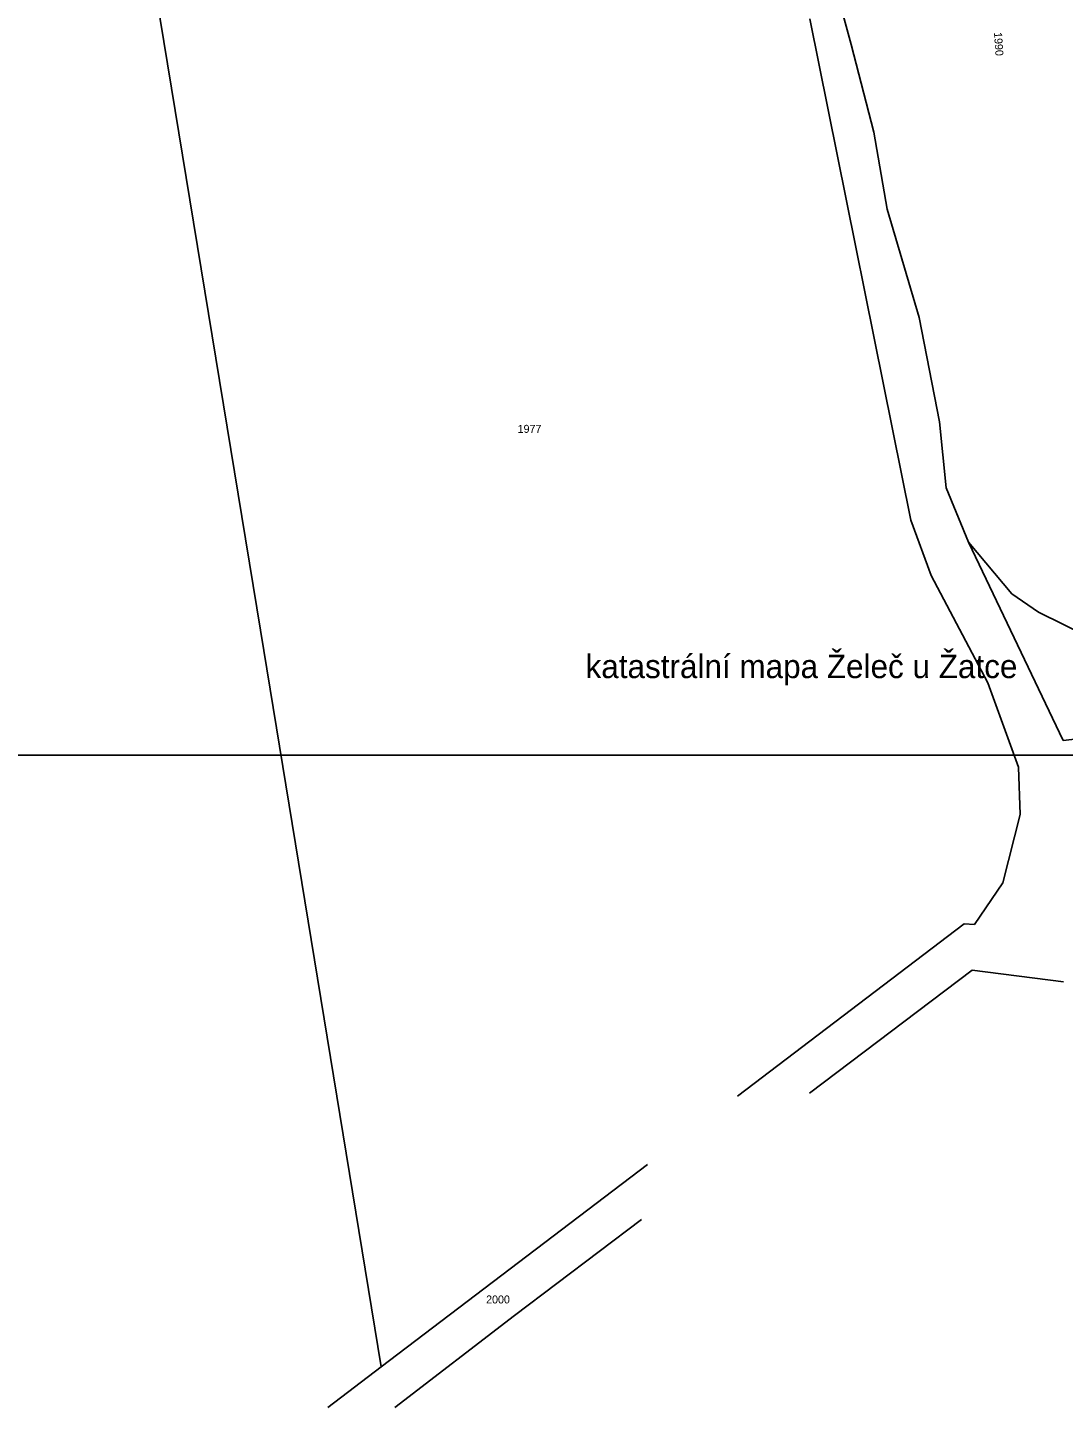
# Model space of a CAD drawing. Extents: x -801853 to -800578, y -1017479 to -1016338.
# Drawn here: x -801170.2 to -800950, y -1017477.7 to -1017184.4 of the extents above; entities that cross this region are included whole.
import ezdxf

# ---------------------------------------------------------------- set-up
doc = ezdxf.new("R2010")
doc.units = 0
for name, color, linetype in [('KLADY_ZMVM', 7, 'Continuous'), ('KN_HRANICE', 7, 'Continuous'), ('KN_PARCELY', 7, 'Continuous'), ('LEGENDA', 7, 'Continuous')]:
    doc.layers.add(name, color=color, linetype=linetype)

msp = doc.modelspace()

# ---------------------------------------------------------------- linework, layer by layer
at = {"layer": 'KN_HRANICE'}
for p, q in [((-801147.67, -1017148.04), (-801120.7, -1017312.51)), ((-801003.34, -1017158.2), (-800995.15, -1017188.06)), ((-801003.97, -1017182.58), (-800982.5, -1017289.15)), ((-800995.15, -1017188.06), (-800990.37, -1017206.68)), ((-800990.37, -1017206.68), (-800987.47, -1017223.03)), ((-800987.47, -1017223.03), (-800980.69, -1017246.06)), ((-800980.69, -1017246.06), (-800976.35, -1017268.19)), ((-800976.35, -1017268.19), (-800974.93, -1017282.28)), ((-800974.93, -1017282.28), (-800970.19, -1017293.76)), ((-800982.5, -1017289.15), (-800978.12, -1017300.9)), ((-800970.19, -1017293.76), (-800961.01, -1017304.78)), ((-800970.19, -1017293.76), (-800950.06, -1017335.93)), ((-800978.12, -1017300.9), (-800966.08, -1017323.69)), ((-800961.01, -1017304.78), (-800955.36, -1017308.64)), ((-800955.36, -1017308.64), (-800944.74, -1017313.92)), ((-801120.7, -1017312.51), (-801095.04, -1017469.02)), ((-800966.08, -1017323.69), (-800959.58, -1017341.61)), ((-800939.16, -1017334.66), (-800950.06, -1017335.93)), ((-800959.58, -1017341.61), (-800959.25, -1017351.67)), ((-800959.25, -1017351.67), (-800962.93, -1017366.17)), ((-800962.93, -1017366.17), (-800968.91, -1017375.05)), ((-801019.33, -1017411.52), (-800971.13, -1017374.91)), ((-800971.13, -1017374.91), (-800968.91, -1017375.05)), ((-801004.03, -1017410.86), (-800969.41, -1017384.77)), ((-800969.41, -1017384.77), (-800950.02, -1017387.19)), ((-801095.04, -1017469.02), (-801038.43, -1017426.03)), ((-801066.73, -1017458.1), (-801039.69, -1017437.72)), ((-801092.18, -1017477.65), (-801066.73, -1017458.1)), ((-801106.41, -1017477.65), (-801095.04, -1017469.02))]:
    msp.add_line(p, q, dxfattribs=at)
at = {"layer": 'LEGENDA'}
msp.add_lwpolyline([(-801559.16, -1017339.08), (-800718.16, -1017339.08), (-800718.16, -1016745.08), (-801559.16, -1016745.08)], close=True, dxfattribs=at)

# ---------------------------------------------------------------- texts
at = {"layer": 'KLADY_ZMVM'}
msp.add_text('katastrální mapa Želeč u Žatce', height=5, dxfattribs=at).set_placement((-801051.61, -1017322.68))
at = {"layer": 'KN_PARCELY'}
msp.add_text('1990', height=1.7, rotation=273.759, dxfattribs=at).set_placement((-800964.8, -1017185.47))
for s, p in [('1977', (-801066.05, -1017270.56)), ('2000', (-801072.75, -1017455.56))]:
    msp.add_text(s, height=1.7, dxfattribs=at).set_placement(p)

doc.saveas('drawing.dxf')
